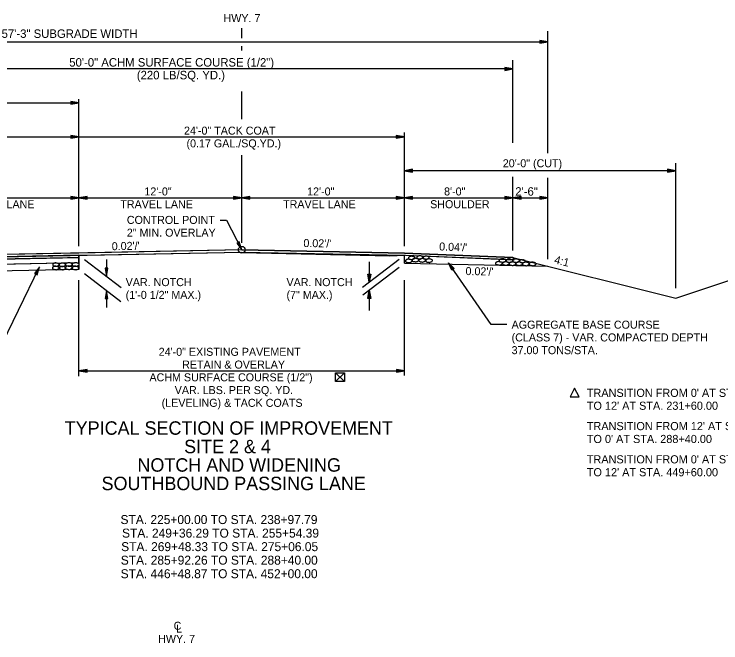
# Model space of a CAD drawing. Extents: x 1398183 to 1398373, y 1967240 to 1968889.
# Drawn here: x 1398239.6 to 1398291.7, y 1968224.5 to 1968270.8 of the extents above; entities that cross this region are included whole.
import ezdxf

# ---------------------------------------------------------------- set-up
doc = ezdxf.new("R2010")
doc.units = 0
for name, color, linetype in [('1', 7, 'Continuous'), ('10', 7, 'Continuous'), ('19', 7, 'Continuous'), ('42', 7, 'Continuous'), ('7', 7, 'Continuous'), ('Level 1', 7, 'Continuous'), ('Level 9', 7, 'Continuous')]:
    doc.layers.add(name, color=color, linetype=linetype)

# ---------------------------------------------------------------- blocks, each defined once
blk = doc.blocks.new('ROCKS')
at = {"layer": '1'}
blk.add_spline([(0.013, 0.06), (0.053, 0.053), (0.107, 0.033), (0.133, 0.013), (0.133, -0.007), (0.12, -0.033), (0.107, -0.04), (0.073, -0.053), (0.033, -0.067), (0.013, -0.067), (-0.02, -0.06), (-0.06, -0.053), (-0.087, -0.047), (-0.113, -0.02), (-0.113, -0.007), (-0.107, 0.02), (-0.087, 0.033), (-0.067, 0.047), (-0.033, 0.053), (-0.02, 0.06), (0.013, 0.06)], degree=3, dxfattribs=at)

msp = doc.modelspace()

# ---------------------------------------------------------------- linework, layer by layer
at = {"layer": '10'}
for p, q in [((1398263.911, 1968244.387), (1398263.269, 1968243.746)), ((1398263.269, 1968244.387), (1398263.911, 1968243.746)), ((1398263.529, 1968243.746), (1398263.518, 1968243.746))]:
    msp.add_line(p, q, dxfattribs=at)
msp.add_lwpolyline([(1398263.518, 1968243.746), (1398263.269, 1968243.746), (1398263.269, 1968244.387), (1398263.911, 1968244.387), (1398263.911, 1968243.746), (1398263.529, 1968243.746)], dxfattribs=at)
msp.add_lwpolyline([(1398280.893, 1968243.262), (1398280.573, 1968242.62), (1398281.214, 1968242.62)], close=True, dxfattribs=at)
at = {"layer": '19'}
for p, q in [((1398278.916, 1968260.572), (1398278.916, 1968269.564)), ((1398278.316, 1968268.889), (1398278.316, 1968268.679)), ((1398278.916, 1968268.784), (1398278.316, 1968268.889)), ((1398221.615, 1968268.784), (1398278.916, 1968268.784)), ((1398278.756, 1968268.799), (1398278.316, 1968268.834)), ((1398278.316, 1968268.679), (1398278.916, 1968268.784)), ((1398278.316, 1968268.729), (1398278.756, 1968268.769)), ((1398276.345, 1968261.333), (1398276.345, 1968267.431)), ((1398276.345, 1968266.784), (1398226.344, 1968266.784)), ((1398275.745, 1968266.889), (1398275.745, 1968266.679)), ((1398276.345, 1968266.784), (1398275.745, 1968266.889)), ((1398276.185, 1968266.799), (1398275.745, 1968266.834)), ((1398275.745, 1968266.679), (1398276.345, 1968266.784)), ((1398275.745, 1968266.729), (1398276.185, 1968266.769)), ((1398213.729, 1968264.284), (1398244.344, 1968264.284)), ((1398243.744, 1968264.389), (1398243.744, 1968264.179)), ((1398244.344, 1968264.284), (1398243.744, 1968264.389)), ((1398244.184, 1968264.299), (1398243.744, 1968264.334)), ((1398243.744, 1968264.179), (1398244.344, 1968264.284)), ((1398243.744, 1968264.229), (1398244.184, 1968264.269)), ((1398244.344, 1968253.717), (1398244.344, 1968264.56)), ((1398268.344, 1968253.717), (1398268.344, 1968262.109)), ((1398215.549, 1968261.784), (1398268.344, 1968261.784)), ((1398243.744, 1968261.889), (1398243.744, 1968261.679)), ((1398244.344, 1968261.784), (1398243.744, 1968261.889)), ((1398244.184, 1968261.799), (1398243.744, 1968261.834)), ((1398243.744, 1968261.679), (1398244.344, 1968261.784)), ((1398243.744, 1968261.729), (1398244.184, 1968261.769)), ((1398267.744, 1968261.889), (1398267.744, 1968261.679)), ((1398268.344, 1968261.784), (1398267.744, 1968261.889)), ((1398268.184, 1968261.799), (1398267.744, 1968261.834)), ((1398267.744, 1968261.679), (1398268.344, 1968261.784)), ((1398267.744, 1968261.729), (1398268.184, 1968261.769)), ((1398288.345, 1968250.625), (1398288.345, 1968259.831)), ((1398268.945, 1968259.389), (1398268.345, 1968259.284)), ((1398288.345, 1968259.284), (1398268.345, 1968259.284)), ((1398268.345, 1968259.284), (1398268.945, 1968259.179)), ((1398268.945, 1968259.334), (1398268.505, 1968259.299)), ((1398268.505, 1968259.269), (1398268.945, 1968259.229)), ((1398268.945, 1968259.179), (1398268.945, 1968259.389)), ((1398287.745, 1968259.389), (1398287.745, 1968259.179)), ((1398288.345, 1968259.284), (1398287.745, 1968259.389)), ((1398288.185, 1968259.299), (1398287.745, 1968259.334)), ((1398287.745, 1968259.179), (1398288.345, 1968259.284)), ((1398287.745, 1968259.229), (1398288.185, 1968259.269)), ((1398276.344, 1968253.397), (1398276.344, 1968258.822)), ((1398278.917, 1968252.754), (1398278.917, 1968258.769)), ((1398232.344, 1968257.284), (1398244.344, 1968257.284)), ((1398243.744, 1968257.389), (1398243.744, 1968257.179)), ((1398244.344, 1968257.284), (1398243.744, 1968257.389)), ((1398244.184, 1968257.299), (1398243.744, 1968257.334)), ((1398243.744, 1968257.179), (1398244.344, 1968257.284)), ((1398243.744, 1968257.229), (1398244.184, 1968257.269)), ((1398244.944, 1968257.389), (1398244.344, 1968257.284)), ((1398244.344, 1968257.284), (1398256.344, 1968257.284)), ((1398244.344, 1968257.284), (1398244.944, 1968257.179)), ((1398244.944, 1968257.334), (1398244.504, 1968257.299)), ((1398244.504, 1968257.269), (1398244.944, 1968257.229)), ((1398244.944, 1968257.179), (1398244.944, 1968257.389)), ((1398255.744, 1968257.389), (1398255.744, 1968257.179)), ((1398256.344, 1968257.284), (1398255.744, 1968257.389)), ((1398256.184, 1968257.299), (1398255.744, 1968257.334)), ((1398255.744, 1968257.179), (1398256.344, 1968257.284)), ((1398255.744, 1968257.229), (1398256.184, 1968257.269)), ((1398256.944, 1968257.389), (1398256.344, 1968257.284)), ((1398256.344, 1968257.284), (1398256.944, 1968257.179)), ((1398256.344, 1968257.284), (1398268.344, 1968257.284)), ((1398256.944, 1968257.334), (1398256.504, 1968257.299)), ((1398256.504, 1968257.269), (1398256.944, 1968257.229)), ((1398256.944, 1968257.179), (1398256.944, 1968257.389)), ((1398267.744, 1968257.389), (1398267.744, 1968257.179)), ((1398268.344, 1968257.284), (1398267.744, 1968257.389)), ((1398268.184, 1968257.299), (1398267.744, 1968257.334)), ((1398267.744, 1968257.179), (1398268.344, 1968257.284)), ((1398267.744, 1968257.229), (1398268.184, 1968257.269)), ((1398268.344, 1968257.284), (1398276.344, 1968257.284)), ((1398268.945, 1968257.389), (1398268.345, 1968257.284)), ((1398268.345, 1968257.284), (1398268.945, 1968257.179)), ((1398268.945, 1968257.334), (1398268.505, 1968257.299)), ((1398268.505, 1968257.269), (1398268.945, 1968257.229)), ((1398268.945, 1968257.179), (1398268.945, 1968257.389)), ((1398275.744, 1968257.389), (1398275.744, 1968257.179)), ((1398276.344, 1968257.284), (1398275.744, 1968257.389)), ((1398276.184, 1968257.299), (1398275.744, 1968257.334)), ((1398275.744, 1968257.179), (1398276.344, 1968257.284)), ((1398275.744, 1968257.229), (1398276.184, 1968257.269)), ((1398276.944, 1968257.389), (1398276.344, 1968257.284)), ((1398276.344, 1968257.284), (1398278.917, 1968257.284)), ((1398276.344, 1968257.284), (1398276.944, 1968257.179)), ((1398276.944, 1968257.334), (1398276.504, 1968257.299)), ((1398276.504, 1968257.269), (1398276.944, 1968257.229)), ((1398276.944, 1968257.179), (1398276.944, 1968257.389)), ((1398278.316, 1968257.389), (1398278.316, 1968257.179)), ((1398278.916, 1968257.284), (1398278.316, 1968257.389)), ((1398278.756, 1968257.299), (1398278.316, 1968257.334)), ((1398278.316, 1968257.179), (1398278.916, 1968257.284)), ((1398278.316, 1968257.229), (1398278.756, 1968257.269)), ((1398256.167, 1968254.039), (1398255.981, 1968253.944)), ((1398255.981, 1968253.944), (1398256.345, 1968253.457)), ((1398256.023, 1968253.962), (1398256.259, 1968253.593)), ((1398256.282, 1968253.603), (1398256.121, 1968254.011)), ((1398256.345, 1968253.457), (1398256.167, 1968254.039)), ((1398256.345, 1968253.457), (1398268.345, 1968253.217)), ((1398288.345, 1968249.897), (1398299.184, 1968253.51)), ((1398232.175, 1968252.637), (1398244.345, 1968252.882)), ((1398243.5, 1968252.865), (1398232.743, 1968252.646)), ((1398244.345, 1968252.882), (1398243.5, 1968252.865)), ((1398244.345, 1968253.049), (1398244.345, 1968252.882)), ((1398244.345, 1968252.882), (1398244.345, 1968252.507)), ((1398244.345, 1968252.507), (1398244.345, 1968252.882)), ((1398244.742, 1968252.746), (1398247.444, 1968250.678)), ((1398246.373, 1968252.747), (1398246.373, 1968251.497)), ((1398267.948, 1968252.746), (1398265.245, 1968250.678)), ((1398268.345, 1968253.217), (1398276.345, 1968252.897)), ((1398268.345, 1968252.465), (1398268.345, 1968253.048)), ((1398276.345, 1968252.897), (1398288.345, 1968249.897)), ((1398276.345, 1968252.897), (1398276.43, 1968252.727)), ((1398231.985, 1968252.258), (1398244.345, 1968252.507)), ((1398236.226, 1968241.495), (1398241.438, 1968252.202)), ((1398241.438, 1968252.202), (1398241.074, 1968251.713)), ((1398241.261, 1968251.621), (1398241.438, 1968252.202)), ((1398241.985, 1968252.457), (1398244.345, 1968252.507)), ((1398244.345, 1968252.507), (1398244.345, 1968252.007)), ((1398265.747, 1968252.562), (1398265.747, 1968251.062)), ((1398268.345, 1968252.465), (1398278.917, 1968252.254)), ((1398274.736, 1968247.952), (1398271.591, 1968252.504)), ((1398271.844, 1968251.952), (1398271.591, 1968252.504)), ((1398271.591, 1968252.504), (1398272.017, 1968252.068)), ((1398271.884, 1968251.98), (1398271.668, 1968252.363)), ((1398271.691, 1968252.38), (1398271.971, 1968252.041)), ((1398241.074, 1968251.713), (1398241.261, 1968251.621)), ((1398241.356, 1968252.065), (1398241.123, 1968251.692)), ((1398241.217, 1968251.643), (1398241.381, 1968252.052)), ((1398244.742, 1968251.703), (1398247.423, 1968249.651)), ((1398246.478, 1968252.097), (1398246.268, 1968252.097)), ((1398246.268, 1968252.097), (1398246.373, 1968251.497)), ((1398246.323, 1968252.097), (1398246.358, 1968251.657)), ((1398246.373, 1968251.497), (1398246.478, 1968252.097)), ((1398246.388, 1968251.657), (1398246.428, 1968252.097)), ((1398267.948, 1968252.161), (1398265.266, 1968250.108)), ((1398265.642, 1968251.662), (1398265.852, 1968251.662)), ((1398265.747, 1968251.062), (1398265.642, 1968251.662)), ((1398265.732, 1968251.222), (1398265.692, 1968251.662)), ((1398265.852, 1968251.662), (1398265.747, 1968251.062)), ((1398265.797, 1968251.662), (1398265.762, 1968251.222)), ((1398272.017, 1968252.068), (1398271.844, 1968251.952)), ((1398244.345, 1968244.143), (1398244.345, 1968251.216)), ((1398268.345, 1968244.183), (1398268.345, 1968251.216)), ((1398246.373, 1968250.454), (1398246.268, 1968249.854)), ((1398246.358, 1968250.294), (1398246.323, 1968249.854)), ((1398246.478, 1968249.854), (1398246.373, 1968250.454)), ((1398246.373, 1968250.454), (1398246.373, 1968249.204)), ((1398246.428, 1968249.854), (1398246.388, 1968250.294)), ((1398265.642, 1968249.877), (1398265.747, 1968250.477)), ((1398265.692, 1968249.877), (1398265.732, 1968250.317)), ((1398265.747, 1968250.477), (1398265.852, 1968249.877)), ((1398265.747, 1968250.477), (1398265.747, 1968248.977)), ((1398265.762, 1968250.317), (1398265.797, 1968249.877)), ((1398246.268, 1968249.854), (1398246.478, 1968249.854)), ((1398265.852, 1968249.877), (1398265.642, 1968249.877)), ((1398275.887, 1968247.952), (1398274.736, 1968247.952)), ((1398244.945, 1968244.639), (1398244.345, 1968244.534)), ((1398244.345, 1968244.534), (1398244.945, 1968244.429)), ((1398244.345, 1968244.534), (1398268.345, 1968244.534)), ((1398244.945, 1968244.584), (1398244.505, 1968244.549)), ((1398244.505, 1968244.519), (1398244.945, 1968244.479)), ((1398244.945, 1968244.429), (1398244.945, 1968244.639)), ((1398267.745, 1968244.639), (1398267.745, 1968244.429)), ((1398268.345, 1968244.534), (1398267.745, 1968244.639)), ((1398268.185, 1968244.549), (1398267.745, 1968244.584)), ((1398267.745, 1968244.429), (1398268.345, 1968244.534)), ((1398267.745, 1968244.479), (1398268.185, 1968244.519))]:
    msp.add_line(p, q, dxfattribs=at)
for points in [[(1398254.764, 1968255.633), (1398255.21, 1968255.633), (1398256.343, 1968253.456)], [(1398226.259, 1968252.567), (1398232.26, 1968252.807), (1398256.345, 1968253.29), (1398268.429, 1968253.047), (1398276.43, 1968252.727)], [(1398256.345, 1968253.457), (1398244.345, 1968253.217), (1398232.345, 1968252.977)], [(1398231.985, 1968252.258), (1398232.752, 1968252.274), (1398241.985, 1968252.457)], [(1398244.345, 1968252.007), (1398231.985, 1968251.758), (1398221.59, 1968251.548)]]:
    msp.add_lwpolyline(points, dxfattribs=at)
for points in [[(1398226.259, 1968252.567), (1398232.26, 1968252.807), (1398256.345, 1968253.29), (1398268.429, 1968253.047), (1398276.431, 1968252.725), (1398276.345, 1968252.897), (1398268.345, 1968253.217), (1398256.345, 1968253.457), (1398232.345, 1968252.977), (1398226.345, 1968252.737)], [(1398232.26, 1968252.807), (1398232.175, 1968252.637), (1398232.987, 1968252.653), (1398241.857, 1968252.832), (1398244.345, 1968252.882), (1398244.345, 1968253.049), (1398243.195, 1968253.026), (1398232.928, 1968252.82)]]:
    msp.add_lwpolyline(points, close=True, dxfattribs=at)
at = {"layer": '42'}
for points in [[(1398256.351, 1968253.253), (1398244.657, 1968253.028), (1398244.345, 1968253.049)], [(1398256.351, 1968253.253), (1398267.253, 1968252.999), (1398268.345, 1968253.048)]]:
    msp.add_lwpolyline(points, dxfattribs=at)
at = {"layer": '7'}
for p, q in [((1398256.345, 1968269.054), (1398256.345, 1968269.784)), ((1398256.345, 1968268.144), (1398256.345, 1968268.464)), ((1398256.344, 1968263.073), (1398256.344, 1968265.131)), ((1398256.345, 1968253.957), (1398256.344, 1968260.432))]:
    msp.add_line(p, q, dxfattribs=at)
at = {"layer": 'Level 9'}
msp.add_circle((1398256.345, 1968253.457), 0.25, dxfattribs=at)

# ---------------------------------------------------------------- block references
at = {"layer": 'Level 1'}
for p, xscale, yscale, rotation in [((1398268.635, 1968252.641), 2.011654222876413, 2.011654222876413, 1.8263814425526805), ((1398268.847, 1968252.861), 1.8866375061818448, 1.886637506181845, 1.8263814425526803), ((1398269.143, 1968252.704), 2.011654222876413, 2.011654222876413, 1.8263814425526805), ((1398269.455, 1968252.896), 1.851115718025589, 1.851115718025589, 1.8263814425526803), ((1398269.637, 1968252.685), 2.011654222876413, 2.011654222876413, 1.8263814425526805), ((1398269.93, 1968252.883), 1.773922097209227, 1.773922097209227, 1.8263814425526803), ((1398270.135, 1968252.66), 2.011654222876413, 2.011654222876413, 1.8263814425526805), ((1398275.563, 1968252.672), 2.011654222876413, 2.0116542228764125, -0.17361855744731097), ((1398276.063, 1968252.66), 2.011654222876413, 2.0116542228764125, -0.17361855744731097), ((1398276.559, 1968252.66), 2.011654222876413, 2.0116542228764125, -0.17361855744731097), ((1398277.021, 1968252.62), 1.7335100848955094, 1.7335100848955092, -0.173618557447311), ((1398242.613, 1968252.121), 1.9974694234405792, 1.9974694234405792, -0.17361855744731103), ((1398242.622, 1968252.368), 1.907051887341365, 1.9070518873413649, -0.173618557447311), ((1398243.098, 1968252.357), 1.9598639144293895, 1.959863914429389, -0.173618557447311), ((1398243.11, 1968252.112), 1.890205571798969, 1.8902055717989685, -0.17361855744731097), ((1398243.57, 1968252.138), 2.011654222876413, 2.0116542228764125, -0.17361855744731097), ((1398243.579, 1968252.38), 2.011654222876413, 2.0116542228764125, -0.17361855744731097), ((1398244.074, 1968252.12), 2.011654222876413, 2.0116542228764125, -0.17361855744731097), ((1398244.078, 1968252.378), 2.011654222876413, 2.0116542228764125, -0.17361855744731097), ((1398275.293, 1968252.465), 2.011654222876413, 2.0116542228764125, -0.17361855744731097), ((1398275.797, 1968252.454), 2.011654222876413, 2.0116542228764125, -0.17361855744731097), ((1398276.289, 1968252.436), 2.011654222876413, 2.0116542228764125, -0.17361855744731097), ((1398276.779, 1968252.436), 2.011654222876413, 2.0116542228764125, -0.17361855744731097), ((1398277.273, 1968252.417), 2.011654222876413, 2.0116542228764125, -0.17361855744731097), ((1398277.775, 1968252.417), 2.011654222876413, 2.0116542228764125, -0.17361855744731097)]:
    msp.add_blockref('ROCKS', p, dxfattribs=dict(at, xscale=xscale, yscale=yscale, rotation=rotation))

# ---------------------------------------------------------------- texts
at = {"layer": '10'}
for s, height, p in [('20\'-0" (CUT)', 0.59001, (1398275.594, 1968259.536)), ('12\'-0"', 0.59, (1398249.167, 1968257.459)), ('12\'-0"', 0.59, (1398261.167, 1968257.459)), ('8\'-0"', 0.59, (1398271.264, 1968257.459)), ('PASSING LANE', 0.59001, (1398235.274, 1968256.519)), ('TRAVEL LANE', 0.59001, (1398247.394, 1968256.519)), ('TRAVEL LANE', 0.59001, (1398259.394, 1968256.519)), ('SHOULDER', 0.59, (1398270.238, 1968256.519)), ('CONTROL POINT', 0.59001, (1398247.873, 1968255.362)), ('2" MIN. OVERLAY', 0.59001, (1398247.873, 1968254.422)), ('VAR. NOTCH', 0.59, (1398247.787, 1968250.777)), ('VAR. NOTCH', 0.59, (1398259.645, 1968250.777)), ('(1\'-0 1/2" MAX.)', 0.59001, (1398247.787, 1968249.837)), ('(7" MAX.)', 0.59, (1398259.645, 1968249.837))]:
    msp.add_text(s, height=height, dxfattribs=at).set_placement(p)
for s, height, rotation, p in [("0.04'/'", 0.59, 357.7094, (1398270.894, 1968253.41)), ('4:1', 0.59, 345.9638, (1398279.348, 1968252.466)), ('24\'-0" EXISTING PAVEMENT', 0.59001, 0, (1398250.221, 1968245.641)), ('RETAIN & OVERLAY', 0.59001, 0, (1398251.951, 1968244.701)), ('ACHM SURFACE COURSE (1/2")', 0.59001, 0, (1398249.54, 1968243.761)), ('VAR. LBS. PER SQ. YD.', 0.59001, 0, (1398251.403, 1968242.821)), ('(LEVELING) & TACK COATS', 0.59001, 0, (1398250.441, 1968241.881))]:
    msp.add_text(s, height=height, rotation=rotation, dxfattribs=at).set_placement(p)
at = {"layer": '19'}
for s, height, p in [('HWY. 7', 0.59, (1398255.002, 1968270.232)), ('57\'-3" SUBGRADE WIDTH', 0.625, (1398238.639, 1968269.071)), ('50\'-0" ACHM SURFACE COURSE (1/2")', 0.625, (1398243.627, 1968266.956)), ('(220 LB/SQ. YD.)', 0.625, (1398248.607, 1968266.018)), ('2\'-6"', 0.625, (1398276.512, 1968257.442)), ('TYPICAL SECTION OF IMPROVEMENT', 0.98999, (1398243.292, 1968239.823)), ('SITE 2 & 4', 0.99, (1398252.096, 1968238.462)), ('NOTCH AND WIDENING', 0.98999, (1398248.655, 1968237.101)), ('SOUTHBOUND PASSING LANE', 0.98999, (1398246.008, 1968235.739)), ('STA. 225+00.00 TO STA. 238+97.79', 0.65999, (1398247.406, 1968233.241)), ('STA. 249+36.29 TO STA. 255+54.39', 0.65999, (1398247.52, 1968232.244)), ('STA. 269+48.33 TO STA. 275+06.05', 0.65999, (1398247.455, 1968231.246)), ('STA. 285+92.26 TO STA. 288+40.00', 0.65999, (1398247.427, 1968230.249)), ('STA. 446+48.87 TO STA. 452+00.00', 0.65999, (1398247.416, 1968229.251)), ('C', 0.59, (1398251.324, 1968225.45)), ('L', 0.59, (1398251.512, 1968225.239)), ('HWY. 7', 0.59, (1398250.184, 1968224.485))]:
    msp.add_text(s, height=height, dxfattribs=at).set_placement(p)
for s, height, rotation, p in [("0.02'/'", 0.59, 1.1458, (1398246.766, 1968253.421)), ("0.02'/'", 0.59, 358.8542, (1398260.887, 1968253.661)), ("0.02'/'", 0.59, 358.8542, (1398272.842, 1968251.595)), ('AGGREGATE BASE COURSE', 0.59001, 360, (1398276.245, 1968247.642)), ('(CLASS 7) - VAR. COMPACTED DEPTH', 0.59001, 360, (1398276.245, 1968246.702)), ('37.00 TONS/STA.', 0.59001, 360, (1398276.245, 1968245.762))]:
    msp.add_text(s, height=height, rotation=rotation, dxfattribs=at).set_placement(p)
at = {"layer": '42'}
for s, p in [('24\'-0" TACK COAT', (1398252.088, 1968261.942)), ('(0.17 GAL./SQ.YD.)', (1398252.272, 1968261.002))]:
    msp.add_text(s, height=0.59001, rotation=360, dxfattribs=at).set_placement(p)
for s, p in [("TRANSITION FROM 0' AT STA. 225+00.00", (1398281.79, 1968242.612)), ("TO 12' AT STA. 231+60.00", (1398281.79, 1968241.662)), ("TRANSITION FROM 12' AT STA. 286+40.00", (1398281.79, 1968240.162)), ("TO 0' AT STA. 288+40.00", (1398281.79, 1968239.212)), ("TRANSITION FROM 0' AT STA. 443+00.00", (1398281.79, 1968237.712)), ("TO 12' AT STA. 449+60.00", (1398281.79, 1968236.762))]:
    msp.add_text(s, height=0.6, dxfattribs=at).set_placement(p)

doc.saveas('drawing.dxf')
